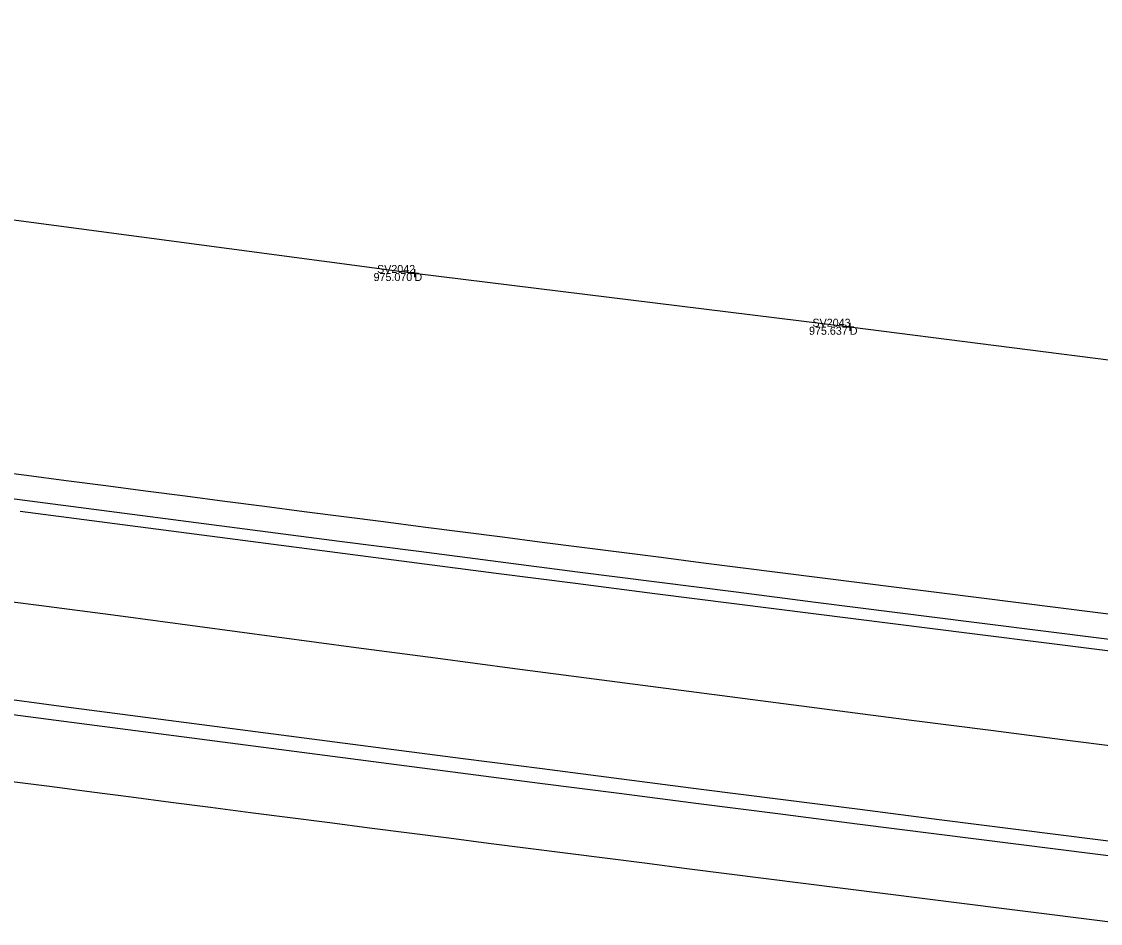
# Model space of a CAD drawing. Extents: x 2065431 to 2068157, y 709104 to 709719.
# Drawn here: x 2066720 to 2066854.9, y 709341 to 709453.6 of the extents above; entities that cross this region are included whole.
import ezdxf

# ---------------------------------------------------------------- set-up
doc = ezdxf.new("R2010")
doc.units = 0
for name, color, linetype in [('DT_X_Terrain_Boundary', 7, 'Continuous'), ('PM_X_Edge_Line', 7, 'Continuous'), ('PM_X_Lane_Line', 7, 'Continuous'), ('PV_X_EOP', 7, 'Continuous'), ('PV_X_Shoulder_Rumble_Strip', 7, 'Continuous'), ('RS_Raster1', 7, 'Continuous'), ('RW_X_Fee_WL', 7, 'Continuous'), ('SV_X_Mon_Cells_Found', 7, 'Continuous'), ('SV_X_Text_Elevation', 7, 'Continuous'), ('SV_X_Text_Name', 7, 'Continuous')]:
    doc.layers.add(name, color=color, linetype=linetype)

msp = doc.modelspace()

# ---------------------------------------------------------------- linework, layer by layer
at = {"layer": 'DT_X_Terrain_Boundary'}
msp.add_lwpolyline([(2066718.86, 709358.69), (2066723.82, 709358.04), (2066728.78, 709357.4), (2066733.73, 709356.75), (2066738.69, 709356.11), (2066743.65, 709355.47), (2066748.61, 709354.82), (2066753.57, 709354.18), (2066758.53, 709353.54), (2066763.49, 709352.9), (2066768.45, 709352.27), (2066773.4, 709351.63), (2066778.36, 709350.99), (2066783.32, 709350.36), (2066788.28, 709349.72), (2066793.24, 709349.09), (2066798.2, 709348.46), (2066803.16, 709347.83), (2066808.12, 709347.2), (2066813.08, 709346.57), (2066818.04, 709345.94), (2066823, 709345.31), (2066827.96, 709344.69), (2066832.93, 709344.06), (2066837.89, 709343.44), (2066842.85, 709342.82), (2066847.81, 709342.19), (2066852.77, 709341.57), (2066857.73, 709340.95)], dxfattribs=at)
at = {"layer": 'PM_X_Edge_Line'}
for points in [[(2066719.82, 709392.43), (2066729.74, 709391.14), (2066739.66, 709389.85), (2066749.57, 709388.56), (2066759.49, 709387.28), (2066769.41, 709386), (2066779.33, 709384.72), (2066789.25, 709383.45), (2066799.17, 709382.18), (2066809.09, 709380.92), (2066819.01, 709379.66), (2066828.93, 709378.4), (2066838.85, 709377.15), (2066848.77, 709375.91), (2066858.69, 709374.66)], [(2066715.69, 709369.33), (2066725.6, 709368.02), (2066735.52, 709366.72), (2066745.43, 709365.43), (2066755.35, 709364.14), (2066765.27, 709362.85), (2066775.19, 709361.57), (2066785.1, 709360.29), (2066795.02, 709359.01), (2066804.94, 709357.74), (2066814.86, 709356.48), (2066824.78, 709355.21), (2066834.7, 709353.95), (2066844.62, 709352.7), (2066854.54, 709351.45), (2066864.46, 709350.2)]]:
    msp.add_lwpolyline(points, dxfattribs=at)
at = {"layer": 'PM_X_Lane_Line'}
msp.add_lwpolyline([(2066712.26, 709381.96), (2066722.18, 709380.69), (2066732.09, 709379.4), (2066742, 709378.07), (2066751.92, 709376.75), (2066761.83, 709375.43), (2066771.74, 709374.11), (2066781.66, 709372.81), (2066791.57, 709371.51), (2066801.49, 709370.21), (2066811.4, 709368.92), (2066821.32, 709367.63), (2066831.24, 709366.35), (2066841.16, 709365.08), (2066851.08, 709363.81), (2066861, 709362.55)], dxfattribs=at)
at = {"layer": 'PV_X_EOP'}
for points in [[(2066715.67, 709397.58), (2066720.62, 709396.93), (2066725.58, 709396.28), (2066730.54, 709395.64), (2066735.5, 709394.99), (2066740.46, 709394.35), (2066745.41, 709393.71), (2066750.37, 709393.06), (2066755.33, 709392.42), (2066760.29, 709391.78), (2066765.25, 709391.14), (2066770.21, 709390.5), (2066775.17, 709389.86), (2066780.13, 709389.23), (2066785.09, 709388.59), (2066790.04, 709387.95), (2066795, 709387.32), (2066799.96, 709386.68), (2066804.92, 709386.05), (2066809.88, 709385.42), (2066814.84, 709384.79), (2066819.8, 709384.16), (2066824.76, 709383.53), (2066829.72, 709382.9), (2066834.69, 709382.27), (2066839.65, 709381.65), (2066844.61, 709381.02), (2066849.57, 709380.4), (2066854.53, 709379.77), (2066859.49, 709379.15)], [(2066718.86, 709358.69), (2066723.82, 709358.04), (2066728.78, 709357.4), (2066733.73, 709356.75), (2066738.69, 709356.11), (2066743.65, 709355.47), (2066748.61, 709354.82), (2066753.57, 709354.18), (2066758.53, 709353.54), (2066763.49, 709352.9), (2066768.45, 709352.27), (2066773.4, 709351.63), (2066778.36, 709350.99), (2066783.32, 709350.36), (2066788.28, 709349.72), (2066793.24, 709349.09), (2066798.2, 709348.46), (2066803.16, 709347.83), (2066808.12, 709347.2), (2066813.08, 709346.57), (2066818.04, 709345.94), (2066823, 709345.31), (2066827.96, 709344.69), (2066832.93, 709344.06), (2066837.89, 709343.44), (2066842.85, 709342.82), (2066847.81, 709342.19), (2066852.77, 709341.57), (2066857.73, 709340.95)]]:
    msp.add_lwpolyline(points, dxfattribs=at)
at = {"layer": 'PV_X_Shoulder_Rumble_Strip'}
for points in [[(2066710.16, 709395.15), (2066720.08, 709393.85), (2066729.99, 709392.56), (2066739.91, 709391.27), (2066749.83, 709389.98), (2066759.74, 709388.7), (2066769.66, 709387.43), (2066779.58, 709386.15), (2066789.5, 709384.88), (2066799.42, 709383.62), (2066809.34, 709382.35), (2066819.26, 709381.09), (2066829.18, 709379.84), (2066839.1, 709378.59), (2066849.02, 709377.34), (2066858.95, 709376.1)], [(2066715.37, 709367.52), (2066725.28, 709366.22), (2066735.2, 709364.92), (2066745.11, 709363.62), (2066755.03, 709362.33), (2066764.95, 709361.04), (2066774.86, 709359.76), (2066784.78, 709358.48), (2066794.7, 709357.21), (2066804.62, 709355.94), (2066814.54, 709354.67), (2066824.46, 709353.41), (2066834.38, 709352.15), (2066844.3, 709350.89), (2066854.22, 709349.64), (2066864.14, 709348.39)]]:
    msp.add_lwpolyline(points, dxfattribs=at)
at = {"layer": 'RS_Raster1'}
for p, q in [((2066768.62, 709422.19), (2066769.62, 709422.19)), ((2066769.12, 709422.69), (2066769.12, 709421.69)), ((2066769.12, 709422.19), (2066769.12, 709422.19)), ((2066823.03, 709415.48), (2066824.03, 709415.48)), ((2066823.53, 709415.98), (2066823.53, 709414.98)), ((2066823.53, 709415.48), (2066823.53, 709415.48))]:
    msp.add_line(p, q, dxfattribs=at)
at = {"layer": 'RW_X_Fee_WL'}
msp.add_lwpolyline([(2066146.22, 709516.28), (2066201.46, 709507.43), (2066256.41, 709499.89), (2066309.66, 709487.73), (2066371.95, 709478.62), (2066434.46, 709468.76), (2066488.47, 709461.11), (2066543.09, 709454.02), (2066597.26, 709445.92), (2066653.85, 709437.6), (2066711.8, 709429.8), (2066769.12, 709422.19), (2066823.53, 709415.48), (2066878.43, 709408.48), (2066947.7, 709399.97)], dxfattribs=at)

# ---------------------------------------------------------------- texts
at = {"layer": 'SV_X_Mon_Cells_Found'}
for s, p in [('SV2042', (2066764.45, 709422.19)), ('SV2043', (2066818.87, 709415.48))]:
    msp.add_text(s, height=1, dxfattribs=at).set_placement(p)
at = {"layer": 'SV_X_Text_Elevation'}
for p in [(2066769.12, 709421.19), (2066823.53, 709414.48)]:
    msp.add_text('D', height=1, dxfattribs=at).set_placement(p)
at = {"layer": 'SV_X_Text_Name'}
for s, p in [('975.070', (2066764.01, 709421.19)), ('975.637', (2066818.44, 709414.48))]:
    msp.add_text(s, height=1, dxfattribs=at).set_placement(p)

doc.saveas('drawing.dxf')
